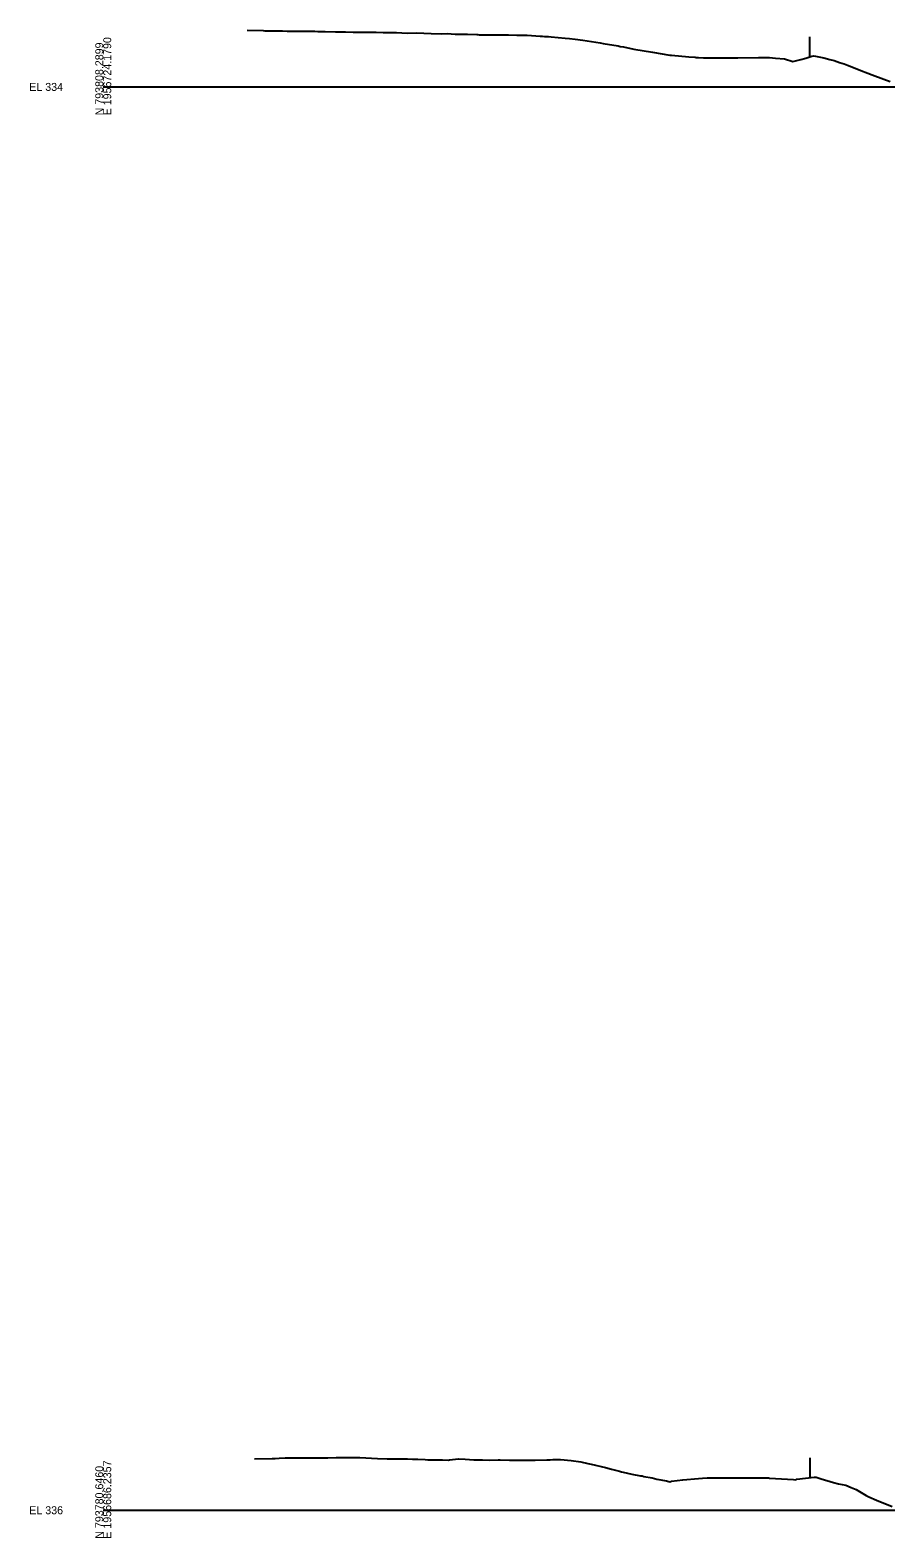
# Model space of a CAD drawing. Extents: x -4026 to 9638, y -10 to 19609.
# Drawn here: x -3026 to -2725, y 2490 to 3020 of the extents above; entities that cross this region are included whole.
import ezdxf

# ---------------------------------------------------------------- set-up
doc = ezdxf.new("R2010")
doc.units = 0
for name, color, linetype in [('Default', 7, 'Continuous'), ('RD_EX_Fence_Other', 7, 'Continuous'), ('RD_GPK_XS_Cell', 7, 'Continuous'), ('RD_XS_ExGround', 7, 'Continuous')]:
    doc.layers.add(name, color=color, linetype=linetype)

msp = doc.modelspace()

# ---------------------------------------------------------------- linework, layer by layer
at = {"layer": 'RD_EX_Fence_Other'}
for p, q in [((-2751.85, 3017.56), (-2751.85, 3010.56)), ((-2751.75, 2518.47), (-2751.75, 2511.47))]:
    msp.add_line(p, q, dxfattribs=at)
at = {"layer": 'RD_GPK_XS_Cell'}
for p, q in [((-3000, 3000), (-2650, 3000)), ((-3000, 2500), (-2650, 2500))]:
    msp.add_line(p, q, dxfattribs=at)
at = {"layer": 'RD_XS_ExGround'}
for points in [[(-2949.43, 3019.93), (-2943.83, 3019.77), (-2943.23, 3019.75), (-2941.54, 3019.72), (-2937.02, 3019.65), (-2935.39, 3019.63), (-2932.76, 3019.63), (-2930.82, 3019.57), (-2929.18, 3019.54), (-2926.95, 3019.53), (-2925.6, 3019.52), (-2924.61, 3019.5), (-2922.03, 3019.47), (-2918.4, 3019.38), (-2914.87, 3019.32), (-2912.2, 3019.28), (-2910.07, 3019.25), (-2907.72, 3019.22), (-2905.99, 3019.18), (-2904.14, 3019.17), (-2901.63, 3019.11), (-2899.78, 3019.08), (-2896.99, 3019.07), (-2893.19, 3018.92), (-2889.84, 3018.95), (-2887.37, 3018.84), (-2884.75, 3018.76), (-2881.17, 3018.69), (-2879.11, 3018.7), (-2876.31, 3018.53), (-2875.53, 3018.51), (-2874.96, 3018.49), (-2871.96, 3018.48), (-2868.75, 3018.35), (-2868.38, 3018.35), (-2867.87, 3018.34), (-2864.8, 3018.31), (-2862.55, 3018.27), (-2861.23, 3018.27), (-2859.43, 3018.26), (-2857.65, 3018.24), (-2854.71, 3018.21), (-2853.6, 3018.2), (-2851.02, 3018.18), (-2846.45, 3017.86), (-2845.61, 3017.8), (-2844.95, 3017.75), (-2844.38, 3017.72), (-2843.53, 3017.65), (-2842.55, 3017.58), (-2837.72, 3017.13), (-2836.19, 3016.96), (-2834.11, 3016.72), (-2831.52, 3016.39), (-2825.37, 3015.47), (-2824.33, 3015.29), (-2819.11, 3014.37), (-2818.31, 3014.23), (-2817.22, 3014.04), (-2813.54, 3013.29), (-2806.95, 3012.18), (-2800.89, 3011.17), (-2800.34, 3011.09), (-2794.28, 3010.54), (-2792.02, 3010.39), (-2791.61, 3010.37), (-2790.86, 3010.31), (-2789.12, 3010.23), (-2787.82, 3010.16), (-2780.96, 3010.22), (-2776.98, 3010.26), (-2769.7, 3010.28), (-2765.87, 3010.29), (-2763.77, 3010.14), (-2760.58, 3009.85), (-2757.72, 3008.93), (-2754.81, 3009.65), (-2753.14, 3010.13), (-2751.7, 3010.61), (-2751.05, 3010.76), (-2750.36, 3010.91), (-2749.7, 3010.79), (-2746.78, 3010.18), (-2744.63, 3009.63), (-2743.2, 3009.25), (-2741.26, 3008.6), (-2739.63, 3008.1), (-2738.43, 3007.68), (-2732.82, 3005.46), (-2732.22, 3005.22), (-2728.9, 3003.85), (-2723.44, 3001.86)], [(-2946.85, 2518.12), (-2940.68, 2518.21), (-2939.61, 2518.23), (-2938.13, 2518.29), (-2936.03, 2518.4), (-2934.51, 2518.42), (-2932.45, 2518.44), (-2929.59, 2518.46), (-2928.87, 2518.47), (-2928.35, 2518.47), (-2925.29, 2518.47), (-2922.18, 2518.47), (-2921.7, 2518.47), (-2921.04, 2518.47), (-2918.12, 2518.48), (-2916.01, 2518.48), (-2914.54, 2518.48), (-2912.5, 2518.48), (-2909.85, 2518.5), (-2903.68, 2518.23), (-2900.22, 2518.1), (-2897.51, 2518.07), (-2896.63, 2518.07), (-2895.42, 2518.05), (-2893.05, 2518.01), (-2891.35, 2517.96), (-2889.47, 2517.91), (-2886.87, 2517.82), (-2885.89, 2517.77), (-2885.18, 2517.75), (-2880.78, 2517.67), (-2878.73, 2517.63), (-2878.33, 2517.71), (-2875.15, 2518.11), (-2872.85, 2517.99), (-2869.79, 2517.76), (-2867.98, 2517.74), (-2866.68, 2517.7), (-2864.4, 2517.63), (-2861.25, 2517.66), (-2860.82, 2517.66), (-2860.51, 2517.66), (-2857.24, 2517.64), (-2854.35, 2517.62), (-2853.66, 2517.61), (-2852.71, 2517.62), (-2848.18, 2517.63), (-2844.16, 2517.72), (-2842.91, 2517.77), (-2842.01, 2517.78), (-2839.33, 2517.79), (-2835.62, 2517.53), (-2832.17, 2517.03), (-2829.68, 2516.45), (-2828.59, 2516.21), (-2827.08, 2515.84), (-2825.01, 2515.36), (-2823.51, 2514.99), (-2821.43, 2514.47), (-2818.54, 2513.68), (-2817.85, 2513.49), (-2817.35, 2513.38), (-2814.26, 2512.69), (-2811.18, 2512.14), (-2810.68, 2512.05), (-2809.99, 2511.91), (-2807.1, 2511.36), (-2805.42, 2510.94), (-2802.09, 2510.3), (-2800.93, 2510.03), (-2800.26, 2510.18), (-2796.3, 2510.72), (-2790.83, 2511.15), (-2789.48, 2511.22), (-2787.83, 2511.34), (-2787.31, 2511.34), (-2777.29, 2511.39), (-2768.95, 2511.35), (-2766.18, 2511.35), (-2765.83, 2511.31), (-2757.5, 2510.86), (-2756.57, 2510.72), (-2756.25, 2510.94), (-2750.15, 2511.65), (-2749.51, 2511.65), (-2747.74, 2511.09), (-2743.35, 2509.77), (-2741.65, 2509.33), (-2739.06, 2508.78), (-2737.18, 2508.03), (-2735.47, 2507.28), (-2733.11, 2505.87), (-2731.89, 2505.2), (-2731.01, 2504.75), (-2728.31, 2503.54), (-2722.8, 2501.31)]]:
    msp.add_lwpolyline(points, dxfattribs=at)

# ---------------------------------------------------------------- texts
at = {"layer": 'Default'}
for p in [(-3000, 3000), (-3000, 2500)]:
    msp.add_text('-', height=0.0001, dxfattribs=at).set_placement(p)
at = {"layer": 'RD_GPK_XS_Cell'}
for s, p in [('N 793808.2899', (-3000, 2990)), ('E 1956724.1790', (-2997.2, 2990)), ('E 1956686.2357', (-2997.2, 2490)), ('N 793780.6460', (-3000, 2490))]:
    msp.add_text(s, height=2.8, rotation=90, dxfattribs=at).set_placement(p)
for s, p in [('EL 334', (-3026, 2998.6)), ('EL 336', (-3026, 2498.6))]:
    msp.add_text(s, height=2.8, dxfattribs=at).set_placement(p)

doc.saveas('drawing.dxf')
